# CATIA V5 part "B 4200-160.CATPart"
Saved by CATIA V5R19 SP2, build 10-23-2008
Part number: B 4200-160
Bounding box of the stored display mesh (mm): x -47.487 to 47.487, y -47.487 to 47.487, z 0 to 440
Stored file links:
  C:\Users\Bora\Desktop\3D Katı model\B serisi\B 4200\B 4200-160.CATPart
  C:\Program Files\Dassault Systemes\B19\intel_a\reffiles\standard\MetricThickPitch.txt
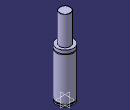
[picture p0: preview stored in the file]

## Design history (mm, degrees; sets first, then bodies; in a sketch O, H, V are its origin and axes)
Body1 (main body)
  Sketch1 on yz-plane, origin (0, 0, 0), H (0, 1, 0), V (0, 0, 1)
    point P1 (47.5, 258.5)
    point P2 (47.5, 253.5)
    point P3 (47.5, 258.5)
    point P6 (47.5, 253.5)
    point P9 (30, 439)
    point P11 (30, 439)
    arc A1 centre (47.5, 256) radius 2.5 from (47.5, 258.5) to (47.5, 253.5) ccw
    line L1 (47.5, 258.5) -> (47.5, 277)
    line L2 (47.5, 13) -> (47.5, 253.5)
    line L3 (43.5, 13) -> (43.5, 8)
    arc A2 centre (29, 439) radius 1 from (30, 439) to (29, 440) ccw
    line L4 (30, 439) -> (30, 277)
    line L5 (47.5, 0) -> (47.5, 8)
    line L6 (29, 440) -> (0, 440)
    point P15 (0, 440)
    line L7 (30, 277) -> (47.5, 277)
    line L8 (0, 0) -> (47.5, 0)
    line L9 (43.5, 13) -> (47.5, 13)
    line L10 (43.5, 8) -> (47.5, 8)
    coincidence: P15 V, P1 P3, P2 P6, P9 P11
    tangency: L6 A2
    horizontal: L7 H, L8 H, L9 H, L10 H
  Shaft1: profile Sketch1, axis Sketch1.V, angle 360
  Sketch2 on face of Shaft1 from Sketch1.L8, origin (0, 0, 0), H (1, 0, 0), V (0, -1, 0)
    point P1 (30, 0)
    distance P1 V = 30
  Hole1: placed by Sketch2, at (30, 0, 0) direction (0, 0, 1), diameter 6.647, depth 13, threaded "M8", thread diameter 8, thread depth 13, pitch 1.25
  CircPattern1: of Hole1, instances 4, angular step 90, axis from xy-plane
